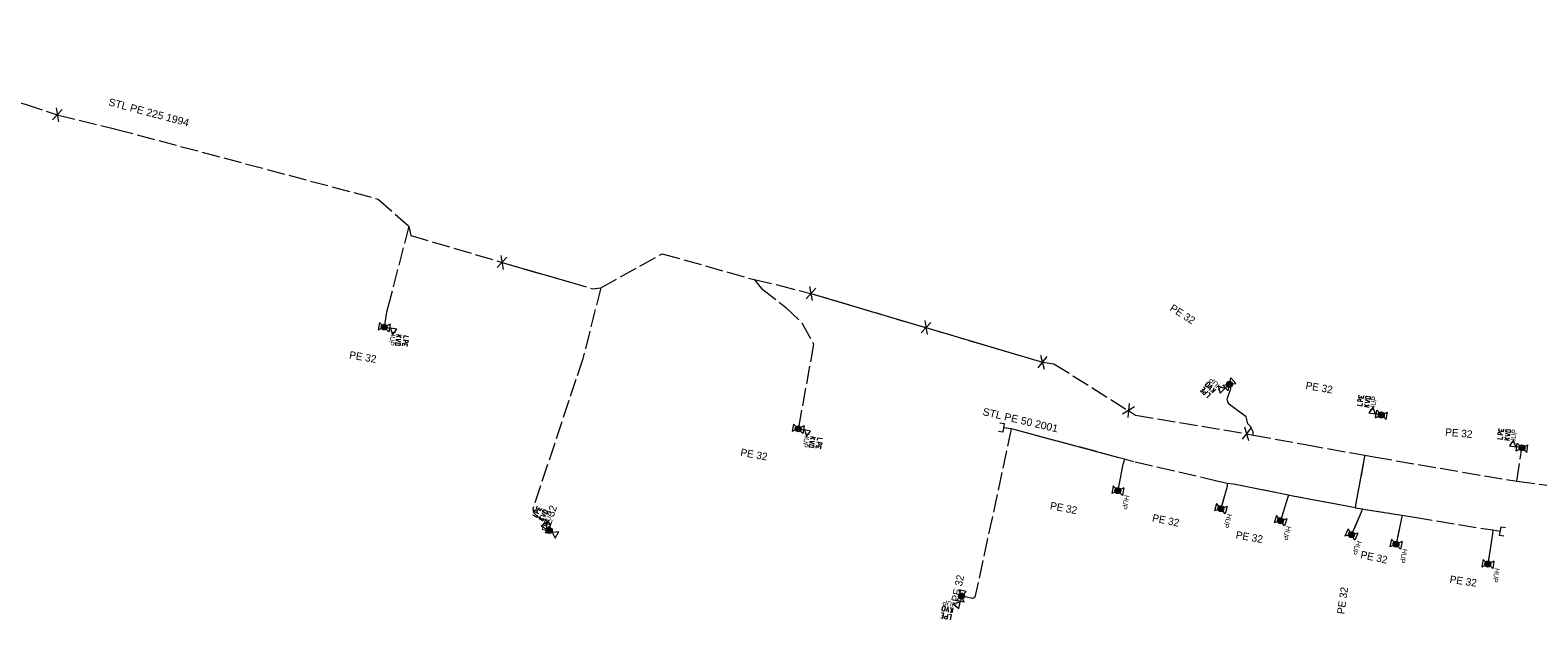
# Model space of a CAD drawing. Extents: x -688140 to -687678, y -1056859 to -1056384.
# Drawn here: x -688002.5 to -687851.2, y -1056686 to -1056626.8 of the extents above; entities that cross this region are included whole.
import ezdxf
from ezdxf.enums import TextEntityAlignment as Align

# ---------------------------------------------------------------- set-up
doc = ezdxf.new("R2010")
doc.units = 0
doc.header["$LTSCALE"] = 0.3
doc.linetypes.add('LONG_DASHED', pattern=[7.5, 6, -1.5])
for name, color, linetype, lineweight in [('13', 7, 'Continuous', 13), ('25', 7, 'Continuous', 13), ('40', 7, 'LONG_DASHED', 13), ('50', 7, 'LONG_DASHED', 13)]:
    doc.layers.add(name, color=color, linetype=linetype, lineweight=lineweight)
doc.layers.add('15', color=7, linetype='Continuous')

msp = doc.modelspace()

# ---------------------------------------------------------------- linework, layer by layer
at = {"layer": '13'}
for p, q in [((-687999.261, -1056634.767), (-688000.219, -1056635.813)), ((-687999.867, -1056634.593), (-687999.613, -1056635.987)), ((-687954.628, -1056649.589), (-687955.59, -1056650.631)), ((-687955.233, -1056649.412), (-687954.985, -1056650.808)), ((-687923.637, -1056652.701), (-687924.581, -1056653.759)), ((-687924.244, -1056652.534), (-687923.974, -1056653.926)), ((-687967.421, -1056656.157), (-687967.537, -1056656.919)), ((-687966.343, -1056656.321), (-687967.537, -1056656.919)), ((-687966.459, -1056657.083), (-687967.421, -1056656.157)), ((-687966.94, -1056656.62), (-687966.317, -1056656.715)), ((-687966.343, -1056656.321), (-687966.459, -1056657.083)), ((-687912.096, -1056656.141), (-687913.062, -1056657.179)), ((-687912.7, -1056655.962), (-687912.458, -1056657.358)), ((-687965.441, -1056658.467), (-687965.748, -1056658.42)), ((-687965.404, -1056657.491), (-687965.726, -1056657.614)), ((-687965.71, -1056658.173), (-687965.403, -1056658.22)), ((-687965.197, -1056657.462), (-687965.691, -1056657.387)), ((-687965.503, -1056657.415), (-687965.227, -1056657.66)), ((-687964.884, -1056658.461), (-687964.86, -1056658.303)), ((-687964.815, -1056658.077), (-687964.791, -1056657.919)), ((-687900.446, -1056659.576), (-687901.33, -1056660.684)), ((-687901.061, -1056659.443), (-687900.715, -1056660.817)), ((-687884.839, -1056662.832), (-687884.73, -1056662.949)), ((-687884.498, -1056662.391), (-687884.272, -1056662.18)), ((-687884.101, -1056662.362), (-687884.328, -1056662.574)), ((-687883.635, -1056662.994), (-687883.998, -1056663.059)), ((-687883.861, -1056663.206), (-687883.496, -1056662.864)), ((-687883.756, -1056663.025), (-687883.653, -1056662.696)), ((-687882.781, -1056662.45), (-687881.459, -1056662.27)), ((-687882.256, -1056663.013), (-687882.781, -1056662.45)), ((-687882.12, -1056662.36), (-687882.581, -1056662.79)), ((-687882.256, -1056663.013), (-687881.984, -1056661.707)), ((-687881.459, -1056662.27), (-687881.984, -1056661.707)), ((-687892.172, -1056664.285), (-687892.328, -1056665.695)), ((-687884.58, -1056663.124), (-687884.471, -1056663.241)), ((-687868.962, -1056663.926), (-687868.989, -1056664.084)), ((-687868.884, -1056663.544), (-687868.912, -1056663.701)), ((-687868.288, -1056664.603), (-687868.559, -1056664.352)), ((-687868.386, -1056664.524), (-687868.062, -1056664.409)), ((-687868.065, -1056663.85), (-687868.37, -1056663.796)), ((-687868.327, -1056663.55), (-687868.022, -1056663.604)), ((-687891.642, -1056664.626), (-687892.858, -1056665.354)), ((-687868.594, -1056664.549), (-687868.101, -1056664.635)), ((-687866.87, -1056665.43), (-687867.491, -1056665.321)), ((-687867.473, -1056665.715), (-687867.34, -1056664.957)), ((-687867.473, -1056665.715), (-687866.267, -1056665.145)), ((-687867.34, -1056664.957), (-687866.4, -1056665.903)), ((-687866.4, -1056665.903), (-687866.267, -1056665.145)), ((-687925.858, -1056666.344), (-687925.995, -1056667.102)), ((-687924.785, -1056666.538), (-687925.995, -1056667.102)), ((-687924.922, -1056667.296), (-687925.858, -1056666.344)), ((-687925.39, -1056666.82), (-687924.77, -1056666.932)), ((-687924.785, -1056666.538), (-687924.922, -1056667.296)), ((-687879.971, -1056666.745), (-687880.827, -1056667.875)), ((-687880.59, -1056666.627), (-687880.208, -1056667.993)), ((-687854.89, -1056667.281), (-687854.913, -1056667.439)), ((-687854.823, -1056666.897), (-687854.846, -1056667.055)), ((-687853.996, -1056667.181), (-687854.302, -1056667.136)), ((-687854.265, -1056666.888), (-687853.959, -1056666.934)), ((-687923.943, -1056668.708), (-687924.248, -1056668.653)), ((-687923.879, -1056667.734), (-687924.204, -1056667.848)), ((-687924.204, -1056668.407), (-687923.899, -1056668.462)), ((-687923.671, -1056667.711), (-687924.163, -1056667.622)), ((-687923.976, -1056667.655), (-687923.707, -1056667.907)), ((-687923.386, -1056668.718), (-687923.358, -1056668.56)), ((-687923.307, -1056668.336), (-687923.278, -1056668.178)), ((-687854.506, -1056667.894), (-687854.011, -1056667.968)), ((-687854.199, -1056667.94), (-687854.477, -1056667.696)), ((-687854.299, -1056667.864), (-687853.978, -1056667.74)), ((-687852.76, -1056668.73), (-687853.383, -1056668.637)), ((-687853.356, -1056669.031), (-687853.242, -1056668.269)), ((-687853.356, -1056669.031), (-687852.164, -1056668.429)), ((-687853.242, -1056668.269), (-687852.278, -1056669.191)), ((-687852.278, -1056669.191), (-687852.164, -1056668.429)), ((-687893.784, -1056672.55), (-687893.927, -1056673.307)), ((-687892.713, -1056672.753), (-687893.927, -1056673.307)), ((-687892.856, -1056673.51), (-687893.784, -1056672.55)), ((-687892.713, -1056672.753), (-687892.856, -1056673.51)), ((-687951.578, -1056675.104), (-687951.655, -1056675.244)), ((-687951.382, -1056674.766), (-687951.459, -1056674.907)), ((-687950.856, -1056674.951), (-687950.584, -1056675.1)), ((-687883.401, -1056674.322), (-687883.609, -1056675.063)), ((-687882.351, -1056674.617), (-687883.609, -1056675.063)), ((-687882.559, -1056675.358), (-687883.401, -1056674.322)), ((-687882.351, -1056674.617), (-687882.559, -1056675.358)), ((-687951.429, -1056675.812), (-687950.99, -1056676.051)), ((-687951.157, -1056675.96), (-687951.333, -1056675.636)), ((-687951.225, -1056675.855), (-687950.88, -1056675.85)), ((-687950.704, -1056675.319), (-687950.976, -1056675.17)), ((-687950.742, -1056677.276), (-687950.373, -1056676.6)), ((-687950.373, -1056676.6), (-687949.785, -1056677.798)), ((-687877.406, -1056675.52), (-687877.635, -1056676.256)), ((-687876.365, -1056675.844), (-687877.635, -1056676.256)), ((-687876.594, -1056676.58), (-687877.406, -1056675.52)), ((-687876.365, -1056675.844), (-687876.594, -1056676.58)), ((-687950.742, -1056677.276), (-687949.416, -1056677.122)), ((-687950.079, -1056677.199), (-687950.632, -1056676.897)), ((-687949.785, -1056677.798), (-687949.416, -1056677.122)), ((-687870.218, -1056676.881), (-687870.523, -1056677.588)), ((-687869.217, -1056677.312), (-687870.523, -1056677.588)), ((-687869.522, -1056678.019), (-687870.218, -1056676.881)), ((-687869.217, -1056677.312), (-687869.522, -1056678.019)), ((-687865.852, -1056677.909), (-687866.014, -1056678.662)), ((-687864.786, -1056678.138), (-687866.014, -1056678.662)), ((-687864.948, -1056678.891), (-687865.852, -1056677.909)), ((-687864.786, -1056678.138), (-687864.948, -1056678.891)), ((-687856.663, -1056679.939), (-687856.776, -1056680.701)), ((-687855.584, -1056680.099), (-687856.776, -1056680.701)), ((-687855.697, -1056680.861), (-687856.663, -1056679.939)), ((-687855.584, -1056680.099), (-687855.697, -1056680.861)), ((-687909.5, -1056684.063), (-687908.52, -1056683.157)), ((-687908.747, -1056684.223), (-687909.5, -1056684.063)), ((-687908.52, -1056683.157), (-687909.273, -1056682.997)), ((-687908.747, -1056684.223), (-687909.273, -1056682.997)), ((-687909.01, -1056683.61), (-687909.141, -1056684.226)), ((-687910.967, -1056685.556), (-687910.81, -1056685.589)), ((-687910.941, -1056684.999), (-687910.876, -1056684.696)), ((-687910.632, -1056684.748), (-687910.696, -1056685.051)), ((-687910.588, -1056685.647), (-687910.431, -1056685.68)), ((-687909.888, -1056684.998), (-687910.148, -1056685.26)), ((-687909.969, -1056685.093), (-687910.073, -1056684.764)), ((-687909.952, -1056685.301), (-687909.848, -1056684.812))]:
    msp.add_line(p, q, dxfattribs=at)
for points in [[(-687966.317, -1056656.715), (-687966.096, -1056657.386), (-687965.684, -1056656.811)], [(-687882.581, -1056662.79), (-687883.244, -1056662.548), (-687883.048, -1056663.227)], [(-687867.491, -1056665.321), (-687867.697, -1056664.645), (-687868.121, -1056665.211)], [(-687924.77, -1056666.932), (-687924.568, -1056667.609), (-687924.14, -1056667.046)], [(-687853.383, -1056668.637), (-687853.607, -1056667.967), (-687854.016, -1056668.543)], [(-687950.632, -1056676.897), (-687950.611, -1056676.191), (-687951.193, -1056676.59)], [(-687909.141, -1056684.226), (-687909.824, -1056684.408), (-687909.274, -1056684.852)]]:
    msp.add_lwpolyline(points, close=True, dxfattribs=at)
for points in [[(-687965.71, -1056658.173), (-687965.749, -1056658.167), (-687965.772, -1056658.184), (-687965.808, -1056658.219), (-687965.824, -1056658.257), (-687965.831, -1056658.306), (-687965.836, -1056658.336), (-687965.802, -1056658.381), (-687965.786, -1056658.404), (-687965.748, -1056658.42)], [(-687965.254, -1056657.838), (-687965.77, -1056657.901), (-687965.293, -1056658.095)], [(-687965.403, -1056658.22), (-687965.374, -1056658.224), (-687965.347, -1056658.249), (-687965.323, -1056658.293), (-687965.33, -1056658.332), (-687965.337, -1056658.382), (-687965.342, -1056658.411), (-687965.387, -1056658.445), (-687965.41, -1056658.461), (-687965.441, -1056658.467)], [(-687964.636, -1056658.559), (-687964.603, -1056658.342), (-687965.097, -1056658.266), (-687965.133, -1056658.504)], [(-687965.038, -1056657.881), (-687964.544, -1056657.956), (-687964.568, -1056658.114)], [(-687964.485, -1056657.571), (-687964.979, -1056657.495), (-687965.014, -1056657.723)], [(-687964.568, -1056658.114), (-687964.595, -1056658.161), (-687964.68, -1056658.188), (-687964.72, -1056658.182), (-687964.803, -1056658.129), (-687964.815, -1056658.077)], [(-687885.07, -1056662.966), (-687884.92, -1056663.127), (-687884.554, -1056662.785), (-687884.718, -1056662.61)], [(-687884.328, -1056662.574), (-687884.35, -1056662.594), (-687884.385, -1056662.6), (-687884.435, -1056662.591), (-687884.462, -1056662.562), (-687884.496, -1056662.526), (-687884.516, -1056662.504), (-687884.514, -1056662.447), (-687884.513, -1056662.419), (-687884.498, -1056662.391)], [(-687884.121, -1056662.928), (-687883.851, -1056662.484), (-687884.298, -1056662.738)], [(-687884.101, -1056662.362), (-687884.072, -1056662.335), (-687884.071, -1056662.307), (-687884.076, -1056662.257), (-687884.096, -1056662.221), (-687884.13, -1056662.184), (-687884.151, -1056662.163), (-687884.207, -1056662.161), (-687884.236, -1056662.16), (-687884.272, -1056662.18)], [(-687884.763, -1056663.295), (-687884.783, -1056663.245), (-687884.751, -1056663.161), (-687884.722, -1056663.133), (-687884.629, -1056663.101), (-687884.58, -1056663.124)], [(-687884.288, -1056663.071), (-687884.654, -1056663.412), (-687884.763, -1056663.295)], [(-687884.388, -1056663.697), (-687884.022, -1056663.356), (-687884.179, -1056663.188)], [(-687869.303, -1056664.425), (-687868.81, -1056664.511), (-687868.771, -1056664.284)], [(-687868.743, -1056664.127), (-687869.236, -1056664.041), (-687869.208, -1056663.883)], [(-687869.208, -1056663.883), (-687869.18, -1056663.837), (-687869.094, -1056663.812), (-687869.054, -1056663.818), (-687868.973, -1056663.873), (-687868.962, -1056663.926)], [(-687869.13, -1056663.44), (-687869.168, -1056663.656), (-687868.676, -1056663.743), (-687868.634, -1056663.506)], [(-687868.528, -1056664.175), (-687868.011, -1056664.123), (-687868.483, -1056663.919)], [(-687868.37, -1056663.796), (-687868.4, -1056663.791), (-687868.426, -1056663.766), (-687868.449, -1056663.722), (-687868.442, -1056663.682), (-687868.433, -1056663.633), (-687868.428, -1056663.603), (-687868.382, -1056663.571), (-687868.358, -1056663.555), (-687868.327, -1056663.55)], [(-687868.065, -1056663.85), (-687868.026, -1056663.857), (-687868.002, -1056663.84), (-687867.966, -1056663.806), (-687867.949, -1056663.769), (-687867.941, -1056663.719), (-687867.935, -1056663.69), (-687867.968, -1056663.644), (-687867.984, -1056663.62), (-687868.022, -1056663.604)], [(-687905.171, -1056666.227), (-687904.734, -1056666.283), (-687904.846, -1056667.157), (-687905.283, -1056667.101)], [(-687854.666, -1056667.476), (-687855.161, -1056667.402), (-687855.137, -1056667.244)], [(-687855.137, -1056667.244), (-687855.11, -1056667.197), (-687855.025, -1056667.17), (-687854.985, -1056667.176), (-687854.902, -1056667.228), (-687854.89, -1056667.281)], [(-687855.071, -1056666.799), (-687855.103, -1056667.017), (-687854.609, -1056667.09), (-687854.573, -1056666.853)], [(-687854.45, -1056667.518), (-687853.935, -1056667.453), (-687854.412, -1056667.261)], [(-687854.302, -1056667.136), (-687854.332, -1056667.131), (-687854.359, -1056667.107), (-687854.382, -1056667.063), (-687854.376, -1056667.024), (-687854.369, -1056666.974), (-687854.365, -1056666.944), (-687854.319, -1056666.911), (-687854.297, -1056666.894), (-687854.265, -1056666.888)], [(-687853.996, -1056667.181), (-687853.956, -1056667.187), (-687853.933, -1056667.17), (-687853.898, -1056667.135), (-687853.882, -1056667.097), (-687853.875, -1056667.048), (-687853.87, -1056667.018), (-687853.904, -1056666.973), (-687853.921, -1056666.95), (-687853.959, -1056666.934)], [(-687924.204, -1056668.407), (-687924.243, -1056668.4), (-687924.266, -1056668.416), (-687924.303, -1056668.45), (-687924.32, -1056668.487), (-687924.329, -1056668.537), (-687924.334, -1056668.566), (-687924.302, -1056668.613), (-687924.286, -1056668.636), (-687924.248, -1056668.653)], [(-687923.739, -1056668.085), (-687924.256, -1056668.133), (-687923.785, -1056668.34)], [(-687923.899, -1056668.462), (-687923.869, -1056668.467), (-687923.843, -1056668.492), (-687923.821, -1056668.537), (-687923.828, -1056668.577), (-687923.837, -1056668.626), (-687923.842, -1056668.655), (-687923.889, -1056668.687), (-687923.912, -1056668.704), (-687923.943, -1056668.708)], [(-687923.141, -1056668.823), (-687923.102, -1056668.606), (-687923.594, -1056668.517), (-687923.637, -1056668.754)], [(-687923.524, -1056668.134), (-687923.032, -1056668.223), (-687923.061, -1056668.38)], [(-687922.963, -1056667.839), (-687923.455, -1056667.75), (-687923.496, -1056667.976)], [(-687923.061, -1056668.38), (-687923.089, -1056668.426), (-687923.175, -1056668.451), (-687923.215, -1056668.444), (-687923.296, -1056668.388), (-687923.307, -1056668.336)], [(-687855.218, -1056667.788), (-687854.724, -1056667.862), (-687854.69, -1056667.634)], [(-687951.435, -1056675.364), (-687951.874, -1056675.124), (-687951.797, -1056674.984)], [(-687951.797, -1056674.984), (-687951.756, -1056674.95), (-687951.666, -1056674.953), (-687951.631, -1056674.972), (-687951.571, -1056675.05), (-687951.578, -1056675.104)], [(-687951.581, -1056674.589), (-687951.687, -1056674.782), (-687951.248, -1056675.022), (-687951.133, -1056674.811)], [(-687950.976, -1056675.17), (-687951.002, -1056675.156), (-687951.019, -1056675.124), (-687951.026, -1056675.075), (-687951.007, -1056675.039), (-687950.983, -1056674.996), (-687950.969, -1056674.969), (-687950.915, -1056674.953), (-687950.887, -1056674.945), (-687950.856, -1056674.951)], [(-687950.704, -1056675.319), (-687950.669, -1056675.338), (-687950.642, -1056675.33), (-687950.596, -1056675.31), (-687950.568, -1056675.279), (-687950.544, -1056675.235), (-687950.53, -1056675.209), (-687950.546, -1056675.155), (-687950.554, -1056675.128), (-687950.584, -1056675.1)], [(-687952.061, -1056675.466), (-687951.622, -1056675.706), (-687951.512, -1056675.504)], [(-687951.247, -1056675.478), (-687950.741, -1056675.595), (-687951.122, -1056675.25)], [(-687854.583, -1056677.601), (-687855.017, -1056677.524), (-687854.863, -1056676.656), (-687854.429, -1056676.733)], [(-687911.08, -1056685.798), (-687910.865, -1056685.843), (-687910.761, -1056685.354), (-687910.995, -1056685.304)], [(-687910.696, -1056685.051), (-687910.702, -1056685.08), (-687910.728, -1056685.106), (-687910.774, -1056685.127), (-687910.813, -1056685.118), (-687910.862, -1056685.108), (-687910.891, -1056685.102), (-687910.922, -1056685.054), (-687910.937, -1056685.031), (-687910.941, -1056684.999)], [(-687910.632, -1056684.748), (-687910.623, -1056684.709), (-687910.639, -1056684.685), (-687910.672, -1056684.647), (-687910.709, -1056684.629), (-687910.758, -1056684.619), (-687910.787, -1056684.613), (-687910.835, -1056684.643), (-687910.858, -1056684.659), (-687910.876, -1056684.696)], [(-687910.64, -1056685.891), (-687910.684, -1056685.861), (-687910.707, -1056685.775), (-687910.698, -1056685.736), (-687910.641, -1056685.656), (-687910.588, -1056685.647)], [(-687910.379, -1056685.435), (-687910.483, -1056685.924), (-687910.64, -1056685.891)], [(-687910.324, -1056685.222), (-687910.357, -1056684.704), (-687910.578, -1056685.168)], [(-687910.102, -1056686.005), (-687909.998, -1056685.516), (-687910.223, -1056685.469)]]:
    msp.add_lwpolyline(points, dxfattribs=at)
for centre, radius in [((-687966.94, -1056656.62), 0.297), ((-687966.94, -1056656.62), 0.223), ((-687966.94, -1056656.62), 0.223), ((-687966.94, -1056656.62), 0.112), ((-687882.12, -1056662.36), 0.297), ((-687882.12, -1056662.36), 0.223), ((-687882.12, -1056662.36), 0.223), ((-687882.12, -1056662.36), 0.112), ((-687866.87, -1056665.43), 0.297), ((-687866.87, -1056665.43), 0.223), ((-687866.87, -1056665.43), 0.223), ((-687866.87, -1056665.43), 0.112), ((-687925.39, -1056666.82), 0.297), ((-687925.39, -1056666.82), 0.223), ((-687925.39, -1056666.82), 0.223), ((-687925.39, -1056666.82), 0.112), ((-687852.76, -1056668.73), 0.297), ((-687852.76, -1056668.73), 0.223), ((-687852.76, -1056668.73), 0.223), ((-687852.76, -1056668.73), 0.112), ((-687893.32, -1056673.03), 0.297), ((-687893.32, -1056673.03), 0.223), ((-687893.32, -1056673.03), 0.223), ((-687893.32, -1056673.03), 0.112), ((-687882.98, -1056674.84), 0.297), ((-687882.98, -1056674.84), 0.223), ((-687882.98, -1056674.84), 0.223), ((-687882.98, -1056674.84), 0.112), ((-687877, -1056676.05), 0.297), ((-687877, -1056676.05), 0.223), ((-687877, -1056676.05), 0.223), ((-687877, -1056676.05), 0.112), ((-687950.37, -1056677.04), 0.297), ((-687950.37, -1056677.04), 0.223), ((-687950.37, -1056677.04), 0.223), ((-687950.37, -1056677.04), 0.112), ((-687869.87, -1056677.45), 0.297), ((-687869.87, -1056677.45), 0.223), ((-687869.87, -1056677.45), 0.223), ((-687869.87, -1056677.45), 0.112), ((-687865.4, -1056678.4), 0.297), ((-687865.4, -1056678.4), 0.223), ((-687865.4, -1056678.4), 0.223), ((-687865.4, -1056678.4), 0.112), ((-687856.18, -1056680.4), 0.297), ((-687856.18, -1056680.4), 0.223), ((-687856.18, -1056680.4), 0.223), ((-687856.18, -1056680.4), 0.112), ((-687909.01, -1056683.61), 0.297), ((-687909.01, -1056683.61), 0.223), ((-687909.01, -1056683.61), 0.223), ((-687909.01, -1056683.61), 0.112)]:
    msp.add_circle(centre, radius, dxfattribs=at)
at = {"layer": '25'}
for p, q in [((-687955.109, -1056650.11), (-687948.391, -1056652.074)), ((-687924.109, -1056653.23), (-687912.608, -1056656.651)), ((-687912.579, -1056656.66), (-687900.888, -1056660.13)), ((-687893.3, -1056669.7), (-687903.63, -1056666.92)), ((-687892.85, -1056670.55), (-687893.32, -1056673.03)), ((-687868.58, -1056669.78), (-687869.428, -1056674.301)), ((-687882.36, -1056672.63), (-687882.98, -1056674.84)), ((-687877.011, -1056673.312), (-687881.72, -1056672.38)), ((-687870.347, -1056674.6), (-687875.75, -1056673.57)), ((-687876.3, -1056673.8), (-687877, -1056676.05)), ((-687868.46, -1056674.91), (-687865.498, -1056675.387)), ((-687868.9, -1056675.2), (-687869.87, -1056677.45)), ((-687864.873, -1056675.955), (-687865.4, -1056678.4)), ((-687855.73, -1056677.37), (-687856.18, -1056680.4))]:
    msp.add_line(p, q, dxfattribs=at)
at = {"layer": '40'}
for points in [[(-688050.47, -1056630.1), (-688044.509, -1056631.82), (-688037.39, -1056633.28), (-688037.358, -1056633.286), (-688034.661, -1056633.811), (-688034.22, -1056632.719), (-688032.398, -1056628.063), (-688031.9, -1056626.79), (-688026.09, -1056628.4), (-688018.06, -1056630.31), (-688010.84, -1056632.13), (-688002.98, -1056634.21), (-687999.74, -1056635.29), (-687994.13, -1056636.66), (-687993.912, -1056636.718), (-687967.53, -1056643.76), (-687964.46, -1056646.48), (-687964.27, -1056647.42), (-687955.109, -1056650.11), (-687948.391, -1056652.074), (-687946.08, -1056652.75), (-687945.2, -1056652.67), (-687939.04, -1056649.24)], [(-687939.04, -1056649.24), (-687929.81, -1056651.84), (-687927.47, -1056652.38), (-687924.109, -1056653.23), (-687912.608, -1056656.651), (-687912.579, -1056656.66), (-687900.888, -1056660.13), (-687899.74, -1056660.29), (-687892.25, -1056664.99), (-687891.55, -1056665.45), (-687880.399, -1056667.31), (-687879.74, -1056667.45), (-687874.499, -1056668.398), (-687868.52, -1056669.48), (-687867.61, -1056669.65), (-687853.26, -1056672.09), (-687845.569, -1056673.1), (-687838.621, -1056673.948), (-687834.18, -1056674.49), (-687815.87, -1056675.16), (-687779.92, -1056666.65)], [(-687868.52, -1056669.48), (-687868.58, -1056669.78), (-687869.428, -1056674.301), (-687869.51, -1056674.74), (-687870.347, -1056674.6), (-687875.75, -1056673.57), (-687876.2, -1056673.48), (-687877.02, -1056673.31), (-687881.72, -1056672.38), (-687882.33, -1056672.32), (-687883.228, -1056672.108), (-687883.26, -1056672.1), (-687891.7, -1056670.13), (-687892.66, -1056669.87), (-687893.3, -1056669.7), (-687903.63, -1056666.92), (-687904.01, -1056666.82), (-687904.79, -1056666.72)], [(-687869.51, -1056674.74), (-687868.753, -1056674.859), (-687868.46, -1056674.91), (-687865.498, -1056675.387), (-687864.776, -1056675.503), (-687863.575, -1056675.697), (-687863.56, -1056675.7), (-687856.47, -1056676.86), (-687855.67, -1056676.96), (-687854.94, -1056677.09)]]:
    msp.add_lwpolyline(points, dxfattribs=at)
at = {"layer": '50'}
msp.add_line((-687853.26, -1056672.09), (-687852.76, -1056668.73), dxfattribs=at)
for points in [[(-687964.46, -1056646.48), (-687966.41, -1056654.02), (-687966.71, -1056655.11), (-687966.94, -1056656.62)], [(-687929.81, -1056651.84), (-687929.07, -1056652.74), (-687926.62, -1056654.63), (-687925.03, -1056656.17), (-687923.85, -1056658.32), (-687925.39, -1056666.82)], [(-687945.2, -1056652.67), (-687947, -1056659.78), (-687947.69, -1056661.86), (-687952.03, -1056674.86), (-687951.97, -1056675.24), (-687951.5, -1056675.68), (-687950.54, -1056676.09), (-687950.31, -1056676.35), (-687950.33, -1056676.69), (-687950.37, -1056677.04), (-687950.079, -1056677.199)], [(-687879.74, -1056667.45), (-687879.73, -1056667.13), (-687879.9, -1056666.78), (-687879.98, -1056666.63), (-687880.28, -1056666.33), (-687880.33, -1056666.01), (-687880.43, -1056665.61), (-687881.44, -1056664.87), (-687882.1, -1056664.37), (-687882.28, -1056664.11), (-687882.34, -1056663.83), (-687881.96, -1056662.76), (-687881.98, -1056662.51), (-687882.12, -1056662.36)], [(-687904.01, -1056666.82), (-687906.38, -1056677.85), (-687907.66, -1056683.71), (-687907.88, -1056683.85), (-687909.01, -1056683.61)], [(-687892.66, -1056669.87), (-687892.85, -1056670.55), (-687893.32, -1056673.03)], [(-687882.33, -1056672.32), (-687882.36, -1056672.63), (-687882.98, -1056674.84)], [(-687876.2, -1056673.48), (-687876.3, -1056673.8), (-687877, -1056676.05)], [(-687868.753, -1056674.859), (-687868.9, -1056675.2), (-687869.87, -1056677.45)], [(-687864.776, -1056675.503), (-687864.873, -1056675.955), (-687865.4, -1056678.4)], [(-687855.67, -1056676.96), (-687855.73, -1056677.37), (-687856.18, -1056680.4)]]:
    msp.add_lwpolyline(points, dxfattribs=at)

# ---------------------------------------------------------------- texts
at = {"layer": '13', "width": 0.9}
for rotation, p in [(261.337, (-687966.349, -1056657.722)), (133.024, (-687883.351, -1056662.141)), (80.054, (-687867.436, -1056664.315)), (259.732, (-687924.831, -1056667.938)), (81.538, (-687853.355, -1056667.631)), (259.268, (-687892.769, -1056674.152)), (61.347, (-687950.258, -1056675.962)), (254.329, (-687882.529, -1056676.005)), (252.719, (-687876.581, -1056677.228)), (246.68, (-687869.578, -1056678.665)), (257.842, (-687864.877, -1056679.535)), (261.554, (-687855.585, -1056681.499)), (168.008, (-687910.145, -1056684.136))]:
    msp.add_text('HUP', height=0.5, rotation=rotation, dxfattribs=at).set_placement(p, align=Align.CENTER)
at = {"layer": '15', "width": 1.05}
for s, rotation, p in [('STL PE 225 1994', 345.055, (-687994.666, -1056634.334)), ('STL PE 50 2001', 346.862, (-687906.94, -1056665.428))]:
    msp.add_text(s, height=0.75, rotation=rotation, dxfattribs=at).set_placement(p)
at = {"layer": '15'}
for rotation, p in [(327.43, (-687888.167, -1056654.89)), (350.31, (-687970.485, -1056659.746)), (350.054, (-687874.515, -1056662.811)), (354.81, (-687860.488, -1056667.501)), (349.731, (-687931.235, -1056669.524)), (71.539, (-687950.44, -1056677.248)), (348.96, (-687900.166, -1056674.878)), (348.44, (-687889.916, -1056676.106)), (349.82, (-687881.526, -1056677.816)), (347.844, (-687869.016, -1056679.794)), (77.678, (-687909.309, -1056684.256)), (351.552, (-687860.054, -1056682.283)), (81.87, (-687870.59, -1056685.473))]:
    msp.add_text('PE 32', height=0.75, rotation=rotation, dxfattribs=at).set_placement(p)

doc.saveas('drawing.dxf')
